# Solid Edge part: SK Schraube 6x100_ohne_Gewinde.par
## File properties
Author: fknapp
Template: Normal.par
Last saved by: fknapp
Revision: 22
Application: Solid Edge
Genauigkeit: 0,99
Username: fknapp
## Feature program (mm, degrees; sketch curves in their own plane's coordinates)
sketch for "unnamed RevolvedProtrusion 1" plane through (0, 0, 0) normal (0, 0, 1) x-axis (1, 0, 0)
  line (0, 100) -> (5.5, 100)
  line (5.5, 100) -> (5.5, 99)
  line (5.5, 99) -> (3, 96.5)
  line (3, 96.5) -> (3, 6)
  line (3, 6) -> (0.2, 0)
  line (0.2, 0) -> (0, 0)
  line (0, 100) -> (0, 0)
revolve "unnamed RevolvedProtrusion 1" add full turn 360 deg
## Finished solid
Body 1: solid body, 6 faces, 5 edges, 0 vertices.
  Faces by surface: cone 2, cylinder 2, plane 2
  Edges by curve: circle 5
Bounding box of the edges (mm): 11.000 x 100.000 x 11.000, from (-5.5, 0, -5.5) to (5.5, 100, 5.5).
Cylindrical faces by radius (mm): R3 x1, R5.5 x1
Conical faces (half-angle, radius in mm at the cone's reference point): 25.0169 deg R3 x1, 45 deg R5.5 x1
Planar faces by outward normal: +y 1, -y 1
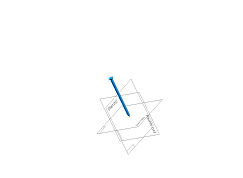
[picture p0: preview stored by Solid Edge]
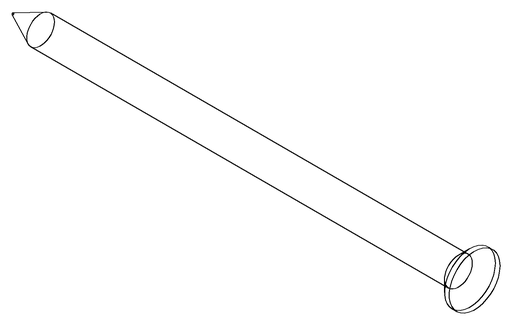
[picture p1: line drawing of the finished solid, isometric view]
